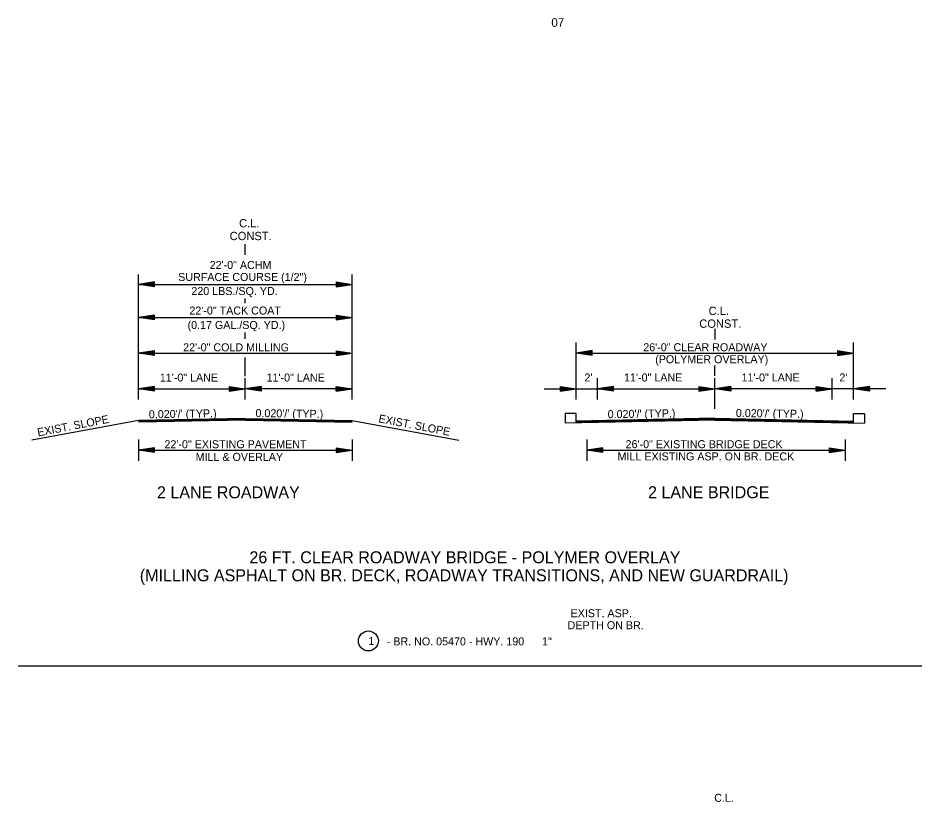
# Model space of a CAD drawing. Extents: x 545241 to 1930787, y -1971772 to 596640.
# Drawn here: x 546887 to 547734, y -1947959 to -1947224 of the extents above; entities that cross this region are included whole.
import ezdxf

# ---------------------------------------------------------------- set-up
doc = ezdxf.new("R2010")
doc.units = 0
for name, color, linetype in [('R_Border', 7, 'Continuous'), ('R_Draft', 7, 'Continuous'), ('R_Grid', 7, 'Continuous')]:
    doc.layers.add(name, color=color, linetype=linetype)

msp = doc.modelspace()

# ---------------------------------------------------------------- linework, layer by layer
at = {"layer": 'R_Border'}
for p, q in [((547539.96, -1947515.11), (547539.96, -1947525.11)), ((547399.8, -1947594.44), (547399.78, -1947603.45)), ((547409.96, -1947594.44), (547399.8, -1947594.44)), ((547409.96, -1947603.07), (547409.96, -1947594.44)), ((547669.96, -1947603.07), (547669.96, -1947594.44)), ((547669.96, -1947594.44), (547680.13, -1947594.44)), ((547680.13, -1947594.44), (547680.14, -1947603.45)), ((546887.2, -1947831.01), (547733.92, -1947831.01))]:
    msp.add_line(p, q, dxfattribs=at)
msp.add_circle((547215.36, -1947807.64), 9.34, dxfattribs=at)
at = {"layer": 'R_Draft'}
for p, q in [((547100.05, -1947445.91), (547100.05, -1947435.91)), ((547000.05, -1947581.43), (547000.05, -1947464.18)), ((547200.05, -1947581.43), (547200.05, -1947464.18)), ((547015.05, -1947471.23), (547000.05, -1947473.48)), ((547015.05, -1947475.73), (547000.05, -1947473.48)), ((547000.05, -1947473.48), (547200.05, -1947473.48)), ((547015.05, -1947471.6), (547002.56, -1947473.48)), ((547015.05, -1947475.35), (547002.56, -1947473.48)), ((547015.05, -1947471.99), (547005.14, -1947473.48)), ((547015.05, -1947474.97), (547005.14, -1947473.48)), ((547015.05, -1947472.36), (547007.63, -1947473.48)), ((547015.05, -1947474.6), (547007.63, -1947473.48)), ((547015.05, -1947472.74), (547010.18, -1947473.48)), ((547015.05, -1947474.21), (547010.18, -1947473.48)), ((547015.05, -1947473.13), (547012.68, -1947473.48)), ((547015.05, -1947473.83), (547012.68, -1947473.48)), ((547015.05, -1947475.73), (547015.05, -1947471.23)), ((547185.05, -1947471.23), (547200.05, -1947473.48)), ((547185.05, -1947471.23), (547185.05, -1947475.73)), ((547185.05, -1947471.6), (547197.55, -1947473.48)), ((547185.05, -1947471.99), (547194.97, -1947473.48)), ((547185.05, -1947472.36), (547192.47, -1947473.48)), ((547185.05, -1947472.75), (547189.93, -1947473.48)), ((547185.05, -1947473.13), (547187.42, -1947473.48)), ((547185.05, -1947475.73), (547200.05, -1947473.48)), ((547185.05, -1947474.21), (547189.93, -1947473.48)), ((547185.05, -1947474.97), (547194.97, -1947473.48)), ((547185.05, -1947475.35), (547197.55, -1947473.48)), ((547185.05, -1947474.6), (547192.47, -1947473.48)), ((547185.05, -1947473.83), (547187.42, -1947473.48)), ((547100.05, -1947491.05), (547100.05, -1947486.64)), ((547015.05, -1947502.28), (547000.05, -1947504.53)), ((547015.05, -1947506.78), (547000.05, -1947504.53)), ((547000.05, -1947504.53), (547200.05, -1947504.53)), ((547015.05, -1947502.65), (547002.56, -1947504.53)), ((547015.05, -1947506.4), (547002.56, -1947504.53)), ((547015.05, -1947503.03), (547005.14, -1947504.53)), ((547015.05, -1947506.02), (547005.14, -1947504.53)), ((547015.05, -1947503.41), (547007.63, -1947504.53)), ((547015.05, -1947505.64), (547007.63, -1947504.53)), ((547015.05, -1947503.79), (547010.18, -1947504.53)), ((547015.05, -1947505.25), (547010.18, -1947504.53)), ((547015.05, -1947504.17), (547012.68, -1947504.53)), ((547015.05, -1947504.88), (547012.68, -1947504.53)), ((547015.05, -1947506.78), (547015.05, -1947502.28)), ((547185.05, -1947502.28), (547200.05, -1947504.53)), ((547185.05, -1947502.28), (547185.05, -1947506.78)), ((547185.05, -1947502.65), (547197.55, -1947504.53)), ((547185.05, -1947503.03), (547194.97, -1947504.53)), ((547185.05, -1947503.41), (547192.47, -1947504.53)), ((547185.05, -1947503.8), (547189.93, -1947504.53)), ((547185.05, -1947504.17), (547187.42, -1947504.53)), ((547185.05, -1947506.78), (547200.05, -1947504.53)), ((547185.05, -1947505.26), (547189.93, -1947504.53)), ((547185.05, -1947506.02), (547194.97, -1947504.53)), ((547185.05, -1947506.4), (547197.55, -1947504.53)), ((547185.05, -1947505.64), (547192.47, -1947504.53)), ((547185.05, -1947504.88), (547187.42, -1947504.53)), ((547100.05, -1947524.52), (547100.05, -1947518.57)), ((547409.96, -1947581.37), (547409.96, -1947527.83)), ((547669.96, -1947581.37), (547669.96, -1947527.83)), ((547015.05, -1947535.64), (547000.05, -1947537.89)), ((547000.05, -1947537.89), (547200.05, -1947537.89)), ((547015.05, -1947540.14), (547000.05, -1947537.89)), ((547015.05, -1947536.02), (547002.56, -1947537.89)), ((547015.05, -1947539.77), (547002.56, -1947537.89)), ((547015.05, -1947536.4), (547005.14, -1947537.89)), ((547015.05, -1947539.38), (547005.14, -1947537.89)), ((547015.05, -1947536.77), (547007.63, -1947537.89)), ((547015.05, -1947539.01), (547007.63, -1947537.89)), ((547015.05, -1947537.16), (547010.18, -1947537.89)), ((547015.05, -1947538.62), (547010.18, -1947537.89)), ((547015.05, -1947537.54), (547012.68, -1947537.89)), ((547015.05, -1947538.24), (547012.68, -1947537.89)), ((547015.05, -1947540.14), (547015.05, -1947535.64)), ((547100.05, -1947549.54), (547100.05, -1947542.13)), ((547185.05, -1947535.64), (547200.05, -1947537.89)), ((547185.05, -1947535.64), (547185.05, -1947540.14)), ((547185.05, -1947536.02), (547197.55, -1947537.89)), ((547185.05, -1947536.4), (547194.97, -1947537.89)), ((547185.05, -1947536.77), (547192.47, -1947537.89)), ((547185.05, -1947537.16), (547189.93, -1947537.89)), ((547185.05, -1947537.54), (547187.42, -1947537.89)), ((547185.05, -1947540.14), (547200.05, -1947537.89)), ((547185.05, -1947538.63), (547189.93, -1947537.89)), ((547185.05, -1947539.38), (547194.97, -1947537.89)), ((547185.05, -1947539.77), (547197.55, -1947537.89)), ((547185.05, -1947539.01), (547192.47, -1947537.89)), ((547185.05, -1947538.24), (547187.42, -1947537.89)), ((547424.96, -1947535.58), (547409.96, -1947537.83)), ((547424.96, -1947540.08), (547409.96, -1947537.83)), ((547424.96, -1947535.96), (547412.47, -1947537.83)), ((547424.96, -1947539.71), (547412.47, -1947537.83)), ((547424.96, -1947536.34), (547415.05, -1947537.83)), ((547424.96, -1947539.32), (547415.05, -1947537.83)), ((547424.96, -1947536.71), (547417.54, -1947537.83)), ((547424.96, -1947538.95), (547417.54, -1947537.83)), ((547419.96, -1947537.83), (547659.96, -1947537.83)), ((547424.96, -1947537.1), (547420.09, -1947537.83)), ((547424.96, -1947538.56), (547420.09, -1947537.83)), ((547424.96, -1947537.48), (547422.59, -1947537.83)), ((547424.96, -1947538.18), (547422.59, -1947537.83)), ((547424.96, -1947540.08), (547424.96, -1947535.58)), ((547654.96, -1947535.58), (547669.96, -1947537.83)), ((547654.96, -1947535.58), (547654.96, -1947540.08)), ((547654.96, -1947535.96), (547667.46, -1947537.83)), ((547654.96, -1947536.34), (547664.88, -1947537.83)), ((547654.96, -1947536.71), (547662.38, -1947537.83)), ((547654.96, -1947537.1), (547659.84, -1947537.83)), ((547654.96, -1947537.48), (547657.33, -1947537.83)), ((547654.96, -1947540.08), (547669.96, -1947537.83)), ((547654.96, -1947538.57), (547659.84, -1947537.83)), ((547654.96, -1947539.32), (547664.88, -1947537.83)), ((547654.96, -1947539.71), (547667.46, -1947537.83)), ((547654.96, -1947538.95), (547662.38, -1947537.83)), ((547654.96, -1947538.18), (547657.33, -1947537.83)), ((547100.05, -1947559.41), (547100.05, -1947549.54)), ((547539.96, -1947559.35), (547539.96, -1947549.48)), ((547100.05, -1947581.43), (547100.05, -1947561.54)), ((547429.96, -1947571.47), (547429.96, -1947561.48)), ((547539.96, -1947590.03), (547539.96, -1947561.48)), ((547649.96, -1947571.43), (547649.96, -1947561.48)), ((547015.05, -1947569.18), (547000.05, -1947571.43)), ((547015.05, -1947573.68), (547000.05, -1947571.43)), ((547000.05, -1947571.43), (547100.05, -1947571.43)), ((547015.05, -1947569.55), (547002.56, -1947571.43)), ((547015.05, -1947573.3), (547002.56, -1947571.43)), ((547015.05, -1947569.94), (547005.14, -1947571.43)), ((547015.05, -1947572.92), (547005.14, -1947571.43)), ((547015.05, -1947570.31), (547007.63, -1947571.43)), ((547015.05, -1947572.55), (547007.63, -1947571.43)), ((547015.05, -1947570.69), (547010.18, -1947571.43)), ((547015.05, -1947572.16), (547010.18, -1947571.43)), ((547015.05, -1947571.08), (547012.68, -1947571.43)), ((547015.05, -1947571.78), (547012.68, -1947571.43)), ((547015.05, -1947573.68), (547015.05, -1947569.18)), ((547085.05, -1947569.18), (547100.05, -1947571.43)), ((547085.05, -1947569.18), (547085.05, -1947573.68)), ((547085.05, -1947569.55), (547097.55, -1947571.43)), ((547085.05, -1947569.94), (547094.97, -1947571.43)), ((547085.05, -1947570.31), (547092.47, -1947571.43)), ((547085.05, -1947570.7), (547089.93, -1947571.43)), ((547085.05, -1947571.08), (547087.42, -1947571.43)), ((547085.05, -1947573.68), (547100.05, -1947571.43)), ((547085.05, -1947572.16), (547089.93, -1947571.43)), ((547085.05, -1947572.92), (547094.97, -1947571.43)), ((547085.05, -1947573.3), (547097.55, -1947571.43)), ((547085.05, -1947572.55), (547092.47, -1947571.43)), ((547085.05, -1947571.78), (547087.42, -1947571.43)), ((547115.05, -1947569.18), (547100.05, -1947571.43)), ((547200.05, -1947571.43), (547100.05, -1947571.43)), ((547115.05, -1947573.68), (547100.05, -1947571.43)), ((547115.05, -1947569.55), (547102.56, -1947571.43)), ((547115.05, -1947573.3), (547102.56, -1947571.43)), ((547115.05, -1947569.94), (547105.14, -1947571.43)), ((547115.05, -1947572.92), (547105.14, -1947571.43)), ((547115.05, -1947570.31), (547107.63, -1947571.43)), ((547115.05, -1947572.55), (547107.63, -1947571.43)), ((547115.05, -1947570.7), (547110.18, -1947571.43)), ((547115.05, -1947572.16), (547110.18, -1947571.43)), ((547115.05, -1947571.08), (547112.68, -1947571.43)), ((547115.05, -1947571.78), (547112.68, -1947571.43)), ((547115.05, -1947569.18), (547115.05, -1947573.68)), ((547185.05, -1947569.18), (547200.05, -1947571.43)), ((547185.05, -1947573.68), (547185.05, -1947569.18)), ((547185.05, -1947569.55), (547197.55, -1947571.43)), ((547185.05, -1947569.94), (547194.97, -1947571.43)), ((547185.05, -1947570.31), (547192.47, -1947571.43)), ((547185.05, -1947570.69), (547189.93, -1947571.43)), ((547185.05, -1947571.08), (547187.42, -1947571.43)), ((547185.05, -1947573.68), (547200.05, -1947571.43)), ((547185.05, -1947572.16), (547189.93, -1947571.43)), ((547185.05, -1947572.92), (547194.97, -1947571.43)), ((547185.05, -1947573.3), (547197.55, -1947571.43)), ((547185.05, -1947572.55), (547192.47, -1947571.43)), ((547185.05, -1947571.78), (547187.42, -1947571.43)), ((547379.96, -1947571.37), (547429.95, -1947571.37)), ((547394.96, -1947569.12), (547409.96, -1947571.37)), ((547394.96, -1947569.12), (547394.96, -1947573.62)), ((547394.96, -1947569.49), (547407.46, -1947571.37)), ((547394.96, -1947569.87), (547404.88, -1947571.37)), ((547394.96, -1947570.25), (547402.38, -1947571.37)), ((547394.96, -1947570.64), (547399.84, -1947571.37)), ((547394.96, -1947571.01), (547397.33, -1947571.37)), ((547394.96, -1947573.62), (547409.96, -1947571.37)), ((547394.96, -1947572.1), (547399.84, -1947571.37)), ((547394.96, -1947572.86), (547404.88, -1947571.37)), ((547394.96, -1947573.24), (547407.46, -1947571.37)), ((547394.96, -1947572.48), (547402.38, -1947571.37)), ((547394.96, -1947571.72), (547397.33, -1947571.37)), ((547429.95, -1947571.37), (547539.96, -1947571.37)), ((547444.96, -1947569.12), (547429.96, -1947571.37)), ((547444.96, -1947573.62), (547429.96, -1947571.37)), ((547429.96, -1947581.37), (547429.96, -1947571.47)), ((547444.96, -1947569.49), (547432.47, -1947571.37)), ((547444.96, -1947573.24), (547432.47, -1947571.37)), ((547444.96, -1947569.87), (547435.05, -1947571.37)), ((547444.96, -1947572.86), (547435.05, -1947571.37)), ((547444.96, -1947570.25), (547437.54, -1947571.37)), ((547444.96, -1947572.48), (547437.54, -1947571.37)), ((547444.96, -1947570.63), (547440.09, -1947571.37)), ((547444.96, -1947572.09), (547440.09, -1947571.37)), ((547444.96, -1947571.01), (547442.59, -1947571.37)), ((547444.96, -1947571.72), (547442.59, -1947571.37)), ((547444.96, -1947573.62), (547444.96, -1947569.12)), ((547524.96, -1947569.12), (547539.96, -1947571.37)), ((547524.96, -1947569.12), (547524.96, -1947573.62)), ((547524.96, -1947569.49), (547537.46, -1947571.37)), ((547524.96, -1947569.87), (547534.88, -1947571.37)), ((547524.96, -1947570.25), (547532.38, -1947571.37)), ((547524.96, -1947570.64), (547529.84, -1947571.37)), ((547524.96, -1947571.01), (547527.33, -1947571.37)), ((547524.96, -1947573.62), (547539.96, -1947571.37)), ((547524.96, -1947572.1), (547529.84, -1947571.37)), ((547524.96, -1947572.86), (547534.88, -1947571.37)), ((547524.96, -1947573.24), (547537.46, -1947571.37)), ((547524.96, -1947572.48), (547532.38, -1947571.37)), ((547524.96, -1947571.72), (547527.33, -1947571.37)), ((547554.96, -1947569.12), (547539.96, -1947571.37)), ((547650, -1947571.37), (547539.96, -1947571.37)), ((547554.96, -1947573.62), (547539.96, -1947571.37)), ((547554.96, -1947569.49), (547542.47, -1947571.37)), ((547554.96, -1947573.24), (547542.47, -1947571.37)), ((547554.96, -1947569.87), (547545.05, -1947571.37)), ((547554.96, -1947572.86), (547545.05, -1947571.37)), ((547554.96, -1947570.25), (547547.54, -1947571.37)), ((547554.96, -1947572.48), (547547.54, -1947571.37)), ((547554.96, -1947570.64), (547550.09, -1947571.37)), ((547554.96, -1947572.1), (547550.09, -1947571.37)), ((547554.96, -1947571.01), (547552.59, -1947571.37)), ((547554.96, -1947571.72), (547552.59, -1947571.37)), ((547554.96, -1947569.12), (547554.96, -1947573.62)), ((547634.96, -1947569.12), (547649.96, -1947571.37)), ((547634.96, -1947573.62), (547634.96, -1947569.12)), ((547634.96, -1947569.49), (547647.46, -1947571.37)), ((547634.96, -1947569.87), (547644.88, -1947571.37)), ((547634.96, -1947570.25), (547642.38, -1947571.37)), ((547634.96, -1947570.63), (547639.84, -1947571.37)), ((547634.96, -1947571.01), (547637.33, -1947571.37)), ((547634.96, -1947573.62), (547649.96, -1947571.37)), ((547634.96, -1947572.09), (547639.84, -1947571.37)), ((547634.96, -1947572.86), (547644.88, -1947571.37)), ((547634.96, -1947573.24), (547647.46, -1947571.37)), ((547634.96, -1947572.48), (547642.38, -1947571.37)), ((547634.96, -1947571.72), (547637.33, -1947571.37)), ((547649.96, -1947581.37), (547649.96, -1947571.43)), ((547699.96, -1947571.37), (547650, -1947571.37)), ((547684.96, -1947569.12), (547669.96, -1947571.37)), ((547684.96, -1947573.62), (547669.96, -1947571.37)), ((547684.96, -1947569.49), (547672.47, -1947571.37)), ((547684.96, -1947573.24), (547672.47, -1947571.37)), ((547684.96, -1947569.87), (547675.05, -1947571.37)), ((547684.96, -1947572.86), (547675.05, -1947571.37)), ((547684.96, -1947570.25), (547677.54, -1947571.37)), ((547684.96, -1947572.48), (547677.54, -1947571.37)), ((547684.96, -1947570.64), (547680.09, -1947571.37)), ((547684.96, -1947572.1), (547680.09, -1947571.37)), ((547684.96, -1947571.01), (547682.59, -1947571.37)), ((547684.96, -1947571.72), (547682.59, -1947571.37)), ((547684.96, -1947569.12), (547684.96, -1947573.62)), ((547000.05, -1947601.04), (546899.98, -1947619.41)), ((547100.05, -1947599.04), (547000.05, -1947601.04)), ((547100.06, -1947599.34), (547000.05, -1947601.34)), ((547100.06, -1947599.63), (547000.05, -1947601.64)), ((547100.07, -1947599.93), (547000.05, -1947601.94)), ((547100.08, -1947600.23), (547000.05, -1947602.24)), ((547100.08, -1947600.53), (547000.05, -1947602.54)), ((547100.09, -1947600.7), (547000.05, -1947602.74)), ((547100.02, -1947600.53), (547200.05, -1947602.54)), ((547100.02, -1947600.7), (547200.05, -1947602.71)), ((547100.03, -1947599.93), (547200.05, -1947601.94)), ((547100.03, -1947600.23), (547200.05, -1947602.24)), ((547100.04, -1947599.63), (547200.05, -1947601.64)), ((547100.05, -1947599.04), (547200.05, -1947601.04)), ((547100.05, -1947599.34), (547200.05, -1947601.34)), ((547200.05, -1947601.04), (547300.12, -1947619.41)), ((547540, -1947600.64), (547399.78, -1947603.45)), ((547539.96, -1947598.97), (547409.96, -1947601.57)), ((547539.97, -1947599.27), (547409.96, -1947601.87)), ((547539.97, -1947599.57), (547409.96, -1947602.17)), ((547539.98, -1947599.87), (547409.96, -1947602.47)), ((547539.99, -1947600.17), (547409.96, -1947602.77)), ((547539.99, -1947600.47), (547409.96, -1947603.07)), ((547539.93, -1947600.47), (547669.96, -1947603.07)), ((547539.93, -1947600.64), (547680.14, -1947603.45)), ((547539.94, -1947599.87), (547669.96, -1947602.47)), ((547539.94, -1947600.17), (547669.96, -1947602.77)), ((547539.95, -1947599.57), (547669.96, -1947602.17)), ((547539.96, -1947598.97), (547669.96, -1947601.57)), ((547539.96, -1947599.27), (547669.96, -1947601.87)), ((547000.05, -1947618.89), (547000.05, -1947638.89)), ((547200.05, -1947618.89), (547200.05, -1947638.89)), ((547419.96, -1947618.83), (547419.96, -1947638.83)), ((547661.96, -1947618.83), (547661.96, -1947638.83)), ((547015.05, -1947626.64), (547000.05, -1947628.89)), ((547015.05, -1947627.02), (547002.56, -1947628.89)), ((547015.05, -1947627.4), (547005.14, -1947628.89)), ((547015.05, -1947631.14), (547015.05, -1947626.64)), ((547185.05, -1947626.64), (547200.05, -1947628.89)), ((547185.05, -1947626.64), (547185.05, -1947631.14)), ((547185.05, -1947627.02), (547197.55, -1947628.89)), ((547185.05, -1947627.4), (547194.97, -1947628.89)), ((547434.96, -1947626.58), (547419.96, -1947628.83)), ((547434.96, -1947626.96), (547422.47, -1947628.83)), ((547434.96, -1947627.34), (547425.05, -1947628.83)), ((547434.96, -1947631.08), (547434.96, -1947626.58)), ((547646.96, -1947626.58), (547661.96, -1947628.83)), ((547646.96, -1947626.58), (547646.96, -1947631.08)), ((547646.96, -1947626.96), (547659.46, -1947628.83)), ((547646.96, -1947627.34), (547656.88, -1947628.83)), ((547000.05, -1947628.89), (547200.05, -1947628.89)), ((547015.05, -1947631.14), (547000.05, -1947628.89)), ((547015.05, -1947630.77), (547002.56, -1947628.89)), ((547015.05, -1947630.39), (547005.14, -1947628.89)), ((547015.05, -1947627.78), (547007.63, -1947628.89)), ((547015.05, -1947630.01), (547007.63, -1947628.89)), ((547015.05, -1947628.16), (547010.18, -1947628.89)), ((547015.05, -1947629.62), (547010.18, -1947628.89)), ((547015.05, -1947628.54), (547012.68, -1947628.89)), ((547015.05, -1947629.25), (547012.68, -1947628.89)), ((547185.05, -1947627.78), (547192.47, -1947628.89)), ((547185.05, -1947628.17), (547189.93, -1947628.89)), ((547185.05, -1947628.54), (547187.42, -1947628.89)), ((547185.05, -1947631.14), (547200.05, -1947628.89)), ((547185.05, -1947629.63), (547189.93, -1947628.89)), ((547185.05, -1947630.39), (547194.97, -1947628.89)), ((547185.05, -1947630.77), (547197.55, -1947628.89)), ((547185.05, -1947630.01), (547192.47, -1947628.89)), ((547185.05, -1947629.25), (547187.42, -1947628.89)), ((547419.96, -1947628.83), (547661.96, -1947628.83)), ((547434.96, -1947631.08), (547419.96, -1947628.83)), ((547434.96, -1947630.71), (547422.47, -1947628.83)), ((547434.96, -1947630.32), (547425.05, -1947628.83)), ((547434.96, -1947627.71), (547427.54, -1947628.83)), ((547434.96, -1947629.95), (547427.54, -1947628.83)), ((547434.96, -1947628.1), (547430.09, -1947628.83)), ((547434.96, -1947629.56), (547430.09, -1947628.83)), ((547434.96, -1947628.48), (547432.59, -1947628.83)), ((547434.96, -1947629.18), (547432.59, -1947628.83)), ((547646.96, -1947627.71), (547654.38, -1947628.83)), ((547646.96, -1947628.1), (547651.84, -1947628.83)), ((547646.96, -1947628.48), (547649.33, -1947628.83)), ((547646.96, -1947631.08), (547661.96, -1947628.83)), ((547646.96, -1947629.57), (547651.84, -1947628.83)), ((547646.96, -1947630.32), (547656.88, -1947628.83)), ((547646.96, -1947630.71), (547659.46, -1947628.83)), ((547646.96, -1947629.95), (547654.38, -1947628.83)), ((547646.96, -1947629.18), (547649.33, -1947628.83))]:
    msp.add_line(p, q, dxfattribs=at)

# ---------------------------------------------------------------- texts
at = {"layer": 'R_Border'}
for s, p in [('1', (547215.36, -1947811.39)), ('C.L.', (547539.36, -1947958.4))]:
    msp.add_text(s, height=7.5, dxfattribs=at).set_placement(p)
at = {"layer": 'R_Draft'}
for s, height, p in [('C.L.', 7.8, (547094.21, -1947420.07)), ('CONST.', 7.8, (547085.42, -1947432.03)), ('22\'-0" ACHM ', 7.5, (547066.66, -1947459.07)), ('SURFACE COURSE (1/2")', 7.5, (547037.19, -1947470.32)), ('220 LBS./SQ. YD. ', 7.5, (547049.56, -1947483.47)), ('22\'-0" TACK COAT', 7.5, (547047.7, -1947501.76)), ('C.L.', 7.8, (547534.12, -1947502.22)), ('(0.17 GAL./SQ. YD.)', 7.5, (547045.96, -1947515.3)), ('CONST.', 7.8, (547525.33, -1947514.18)), ('22\'-0" COLD MILLING', 7.5, (547041.85, -1947536.22)), ('26\'-0" CLEAR ROADWAY ', 7.5, (547472.88, -1947536.16)), ('(POLYMER OVERLAY)', 7.5, (547484.04, -1947547.41)), ('11\'-0" LANE', 7.5, (547019.99, -1947564.57)), ('11\'-0" LANE', 7.5, (547119.99, -1947564.57)), ("2'", 7.5, (547417.78, -1947564.5)), ('11\'-0" LANE', 7.5, (547454.9, -1947564.5)), ('11\'-0" LANE', 7.5, (547564.92, -1947564.5)), ("2'", 7.5, (547656.57, -1947564.5)), ('22\'-0" EXISTING PAVEMENT', 7.5, (547024.33, -1947627.07)), ('26\'-0" EXISTING BRIDGE DECK', 7.5, (547456.34, -1947627)), ('MILL & OVERLAY', 7.5, (547053.53, -1947638.9)), ('MILL EXISTING ASP. ON BR. DECK', 7.5, (547448.81, -1947638.46)), ('2 LANE ROADWAY', 11.25, (547017.33, -1947673.97)), ('2 LANE BRIDGE', 11.25, (547477.37, -1947673.91)), ('26 FT. CLEAR ROADWAY BRIDGE - POLYMER OVERLAY', 11.25, (547103.91, -1947734.89)), ('(MILLING ASPHALT ON BR. DECK, ROADWAY TRANSITIONS, AND NEW GUARDRAIL)', 11.25, (547001.24, -1947751.77)), (' EXIST. ASP. ', 7.5, (547401.99, -1947785.39)), ('DEPTH ON BR. ', 7.5, (547401.99, -1947796.64)), ('- BR. NO. 05470 - HWY. 190      1"', 7.5, (547232.59, -1947811.81))]:
    msp.add_text(s, height=height, dxfattribs=at).set_placement(p)
for s, rotation, p in [("0.020'/' (TYP.)", 0.87191, (547009.78, -1947598.99)), ("0.020'/' (TYP.)", 359.12809, (547109.55, -1947597.76)), ("0.020'/' (TYP.)", 0.87191, (547439.58, -1947598.93)), ("0.020'/' (TYP.)", 359.12809, (547559.56, -1947597.7)), ('EXIST. SLOPE', 10.88286, (546905.96, -1947616.03)), ('EXIST. SLOPE', 349.11714, (547224.43, -1947602.63))]:
    msp.add_text(s, height=7.5, rotation=rotation, dxfattribs=at).set_placement(p)
at = {"layer": 'R_Grid'}
msp.add_text('07', height=8.077, dxfattribs=at).set_placement((547386.77, -1947232.13))

doc.saveas('drawing.dxf')
